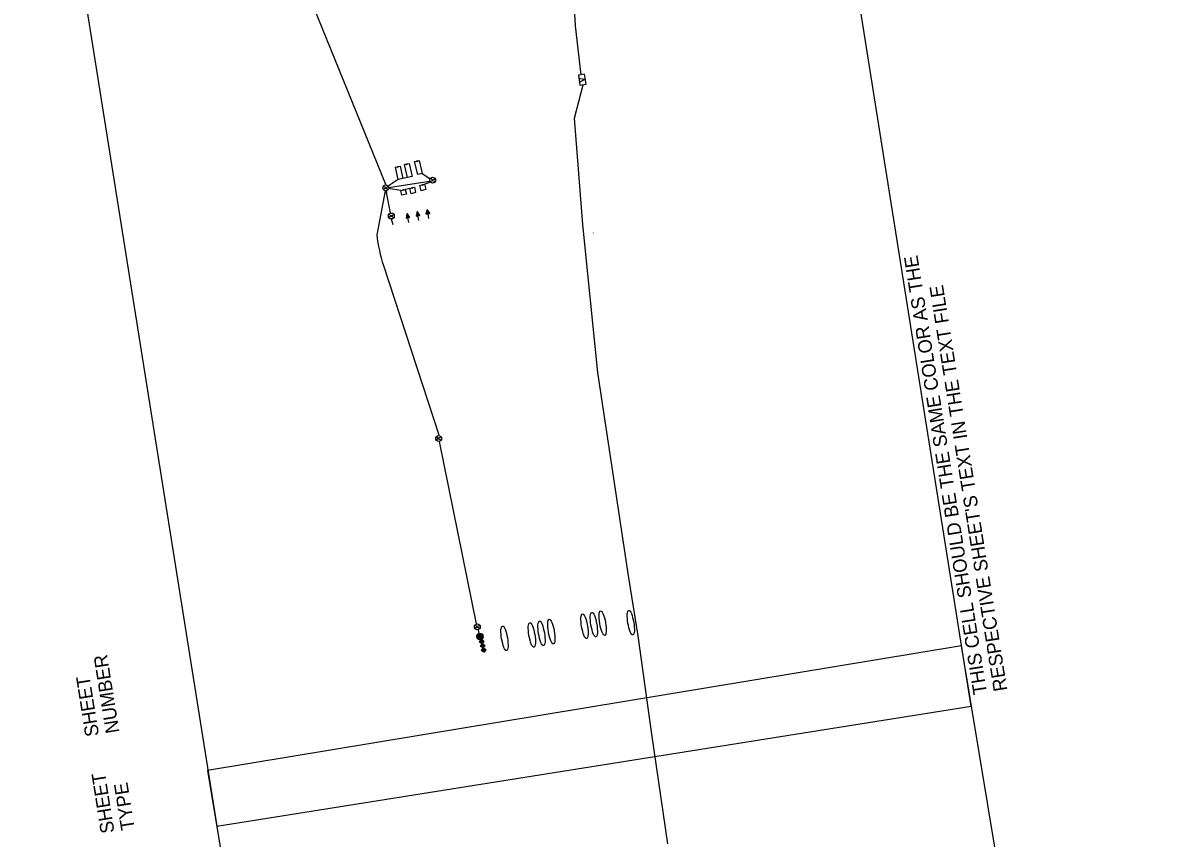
# Model space of a CAD drawing. Extents: x 601462 to 605493, y 331960 to 402715.
# Drawn here: x 603749 to 605204, y 337841 to 338882 of the extents above; entities that cross this region are included whole.
import ezdxf

# ---------------------------------------------------------------- set-up
doc = ezdxf.new("R2010")
doc.units = 0
for name, color, linetype in [('Default', 7, 'Continuous'), ('P_FTMS', 7, 'Continuous'), ('P_FTMSConduit', 7, 'Continuous'), ('P_MISC_TXT_2A (Construction)', 7, 'Continuous'), ('P_MISC_TXT_2B (Construction)', 7, 'Continuous')]:
    doc.layers.add(name, color=color, linetype=linetype)

# ---------------------------------------------------------------- blocks, each defined once
blk = doc.blocks.new('POINT_DISPLAY')
at = {"layer": 'Default'}
blk.add_line((0, 0), (0, 0), dxfattribs=at)
blk = doc.blocks.new('_U222')
at = {"layer": 'P_FTMS'}
for p, q in [((-4.5, 3.2), (1.5, -0.2)), ((-4.4, 2.8), (1.3, -0.4)), ((-4.3, 3.5), (1.8, 0)), ((-3.9, 3.4), (-4.3, 2.6)), ((-4.3, 2.4), (1, -0.6)), ((-3.5, 3.4), (-4.2, 2.2)), ((-4.2, 2), (0.7, -0.8)), ((-3.2, 3.3), (-4.1, 1.7)), ((-4.1, 1.6), (0.5, -1)), ((-2.9, 3.3), (-4, 1.3)), ((-4, 1.2), (0.2, -1.2)), ((-2.6, 3.2), (-3.9, 0.9)), ((-2.2, 3.2), (-3.8, 0.5)), ((-3.8, 0.7), (0, -1.4)), ((-1.9, 3.2), (-3.7, 0.1)), ((-3.7, 0.3), (-0.3, -1.6)), ((-3.5, 3.4), (2, 0.2)), ((-1.6, 3.1), (-3.5, -0.3)), ((-1.3, 3.1), (-3.4, -0.7)), ((-0.9, 3), (-3.3, -1.2)), ((-0.6, 3), (-3.2, -1.6)), ((-0.3, 2.9), (-3.1, -2)), ((0, 2.9), (-3, -2.4)), ((0.4, 2.8), (-2.9, -2.8)), ((-2.7, 3.3), (2.3, 0.4)), ((0.7, 2.8), (-2.7, -3.2)), ((1, 2.8), (-2.5, -3.4)), ((-1.9, 3.2), (2.5, 0.6)), ((1.3, 2.7), (-1.8, -2.9)), ((1.7, 2.7), (-1.2, -2.3)), ((-1.1, 3), (2.8, 0.8)), ((2, 2.6), (-0.5, -1.8)), ((-0.3, 2.9), (3.1, 1)), ((2.3, 2.6), (0.1, -1.3)), ((0.5, 2.8), (3.3, 1.2)), ((2.6, 2.5), (0.7, -0.8)), ((1.3, 2.7), (3.6, 1.4)), ((3, 2.5), (1.4, -0.3)), ((3.3, 2.4), (2, 0.2)), ((2.2, 2.6), (3.8, 1.6)), ((3.6, 2.4), (2.7, 0.7)), ((3, 2.5), (4.1, 1.8)), ((3.9, 2.3), (3.3, 1.2)), ((3.8, 2.4), (4.3, 2.1)), ((4.3, 2.3), (4, 1.7)), ((-3.6, -0.1), (-0.5, -1.8)), ((-3.5, -0.5), (-0.8, -2)), ((-3.4, -0.9), (-1.1, -2.2)), ((-3.3, -1.3), (-1.3, -2.4)), ((-3.2, -1.7), (-1.6, -2.7)), ((-3, -2.2), (-1.8, -2.9)), ((-2.9, -2.6), (-2.1, -3.1)), ((-2.8, -3), (-2.3, -3.3)), ((-2.7, -3.4), (-2.6, -3.5))]:
    blk.add_line(p, q, dxfattribs=at)
blk.add_lwpolyline([(-4.6, 3.5), (4.6, 2.3), (-2.7, -3.5)], close=True, dxfattribs=at)
blk.add_blockref('POINT_DISPLAY', (4.6, 2.3), dxfattribs=at)
blk = doc.blocks.new('FMD')
at = {"layer": 'P_FTMS'}
for p, q in [((16.9, 17.6), (-16.9, 17.6)), ((-16.1, 16.1), (-16.1, 18.4)), ((16.1, 16.1), (-16.1, 16.1)), ((15.5, 19), (-15.5, 19)), ((-14.6, 14.6), (-14.6, 19.9)), ((14.6, 14.6), (-14.6, 14.6)), ((14, 20.5), (-14, 20.5)), ((-13.2, 13.2), (-13.2, 21.3)), ((13.2, 13.2), (-13.2, 13.2)), ((12.5, 21.9), (-12.5, 21.9)), ((-11.7, 11.7), (-11.7, 22.8)), ((11.7, 11.7), (-11.7, 11.7)), ((11.1, 23.4), (-11.1, 23.4)), ((-10.2, 10.2), (-10.2, 24.2)), ((10.2, 10.2), (-10.2, 10.2)), ((9.6, 24.9), (-9.6, 24.9)), ((-8.8, 8.8), (-8.8, 25.7)), ((8.8, 8.8), (-8.8, 8.8)), ((8.2, 26.3), (-8.2, 26.3)), ((-7.3, 7.3), (-7.3, 27.2)), ((7.3, 7.3), (-7.3, 7.3)), ((6.7, 27.8), (-6.7, 27.8)), ((-5.9, 5.9), (-5.9, 28.6)), ((5.9, 5.9), (-5.9, 5.9)), ((5.2, 29.3), (-5.2, 29.3)), ((-4.4, 4.4), (-4.4, 30.1)), ((4.4, 4.4), (-4.4, 4.4)), ((3.8, 30.7), (-3.8, 30.7)), ((-2.9, 2.9), (-2.9, 31.6)), ((2.9, 2.9), (-2.9, 2.9)), ((2.3, 32.2), (-2.3, 32.2)), ((-1.5, 1.5), (-1.5, 33)), ((1.5, 1.5), (-1.5, 1.5)), ((0.8, 33.6), (-0.8, 33.6)), ((0, 0), (0, 34.5)), ((1.5, 1.5), (1.5, 33)), ((2.9, 2.9), (2.9, 31.6)), ((4.4, 4.4), (4.4, 30.1)), ((5.9, 5.9), (5.9, 28.6)), ((7.3, 7.3), (7.3, 27.2)), ((8.8, 8.8), (8.8, 25.7)), ((10.2, 10.2), (10.2, 24.2)), ((11.7, 11.7), (11.7, 22.8)), ((13.2, 13.2), (13.2, 21.3)), ((14.6, 14.6), (14.6, 19.9)), ((16.1, 16.1), (16.1, 18.4))]:
    blk.add_line(p, q, dxfattribs=at)
blk.add_lwpolyline([(-17.2, 17.2), (0, 34.5), (17.2, 17.2), (0, 0)], close=True, dxfattribs=at)
blk = doc.blocks.new('FTMS_FCV')
at = {"layer": 'P_FTMS'}
blk.add_line((12.7, 16.3), (0.6, -21.9), dxfattribs=at)
blk.add_lwpolyline([(39.1, 24.4), (-39.1, 24.4), (-39.1, -24.4), (39.1, -24.4)], close=True, dxfattribs=at)
blk.add_lwpolyline([(-12.1, 16.2), (0.6, -21.9)], dxfattribs=at)

msp = doc.modelspace()

# ---------------------------------------------------------------- linework, layer by layer
at = {"layer": 'P_FTMS'}
for p, q in [((604258.4, 338689.6), (604268.3, 338683.1)), ((604227.9, 338682), (604214.9, 338673.4)), ((604239.6, 338684.5), (604233.8, 338683.4)), ((604261.4, 338675.8), (604268.3, 338678.6)), ((604231, 338667.8), (604215.5, 338670.4)), ((604242.6, 338670.6), (604236.8, 338669.2)), ((604241.3, 338627.1), (604240.1, 338633.1)), ((604254.1, 338629.6), (604252.9, 338635.6)), ((604266.9, 338632), (604265.8, 338638.1)), ((604328.1, 338099.6), (604334.4, 338102)), ((604328.1, 338099.4), (604334.6, 338101.9)), ((604328.1, 338099.1), (604334.8, 338101.7)), ((604328.1, 338098.8), (604335, 338101.5)), ((604328.1, 338098.6), (604335.2, 338101.3)), ((604328.1, 338098.3), (604335.3, 338101.1)), ((604328.1, 338098.1), (604335.4, 338100.9)), ((604329.7, 338095.6), (604328.1, 338099.6)), ((604329.3, 338095.9), (604328.1, 338099.1)), ((604328.9, 338096.4), (604328.1, 338098.5)), ((604328.2, 338099.9), (604334.2, 338102.2)), ((604328.2, 338097.8), (604335.6, 338100.7)), ((604330, 338095.4), (604328.2, 338100)), ((604328.3, 338100.2), (604333.9, 338102.4)), ((604328.3, 338097.6), (604335.7, 338100.5)), ((604328.3, 338097.4), (604335.8, 338100.3)), ((604328.4, 338100.5), (604333.6, 338102.5)), ((604330.4, 338095.2), (604328.4, 338100.4)), ((604328.4, 338097.2), (604335.9, 338100)), ((604330.7, 338095.1), (604328.5, 338100.7)), ((604328.5, 338097), (604335.9, 338099.8)), ((604328.6, 338100.8), (604333.2, 338102.6)), ((604328.6, 338096.7), (604336, 338099.6)), ((604331, 338095), (604328.7, 338100.9)), ((604328.8, 338101.2), (604332.8, 338102.7)), ((604331.2, 338094.9), (604328.8, 338101.2)), ((604328.8, 338096.5), (604336, 338099.3)), ((604328.9, 338096.3), (604336, 338099.1)), ((604331.5, 338094.9), (604329, 338101.4)), ((604329.1, 338096.1), (604336, 338098.8)), ((604329.2, 338101.6), (604332.4, 338102.8)), ((604331.8, 338094.8), (604329.2, 338101.6)), ((604329.3, 338096), (604336, 338098.6)), ((604332, 338094.8), (604329.4, 338101.8)), ((604329.5, 338095.8), (604336, 338098.3)), ((604332.3, 338094.8), (604329.6, 338101.9)), ((604329.7, 338102), (604331.7, 338102.8)), ((604329.7, 338095.6), (604336, 338098)), ((604332.5, 338094.9), (604329.8, 338102.1)), ((604329.9, 338095.4), (604335.9, 338097.7)), ((604332.8, 338094.9), (604330, 338102.2)), ((604333, 338095), (604330.2, 338102.3)), ((604330.2, 338095.3), (604335.8, 338097.4)), ((604333.3, 338095), (604330.4, 338102.5)), ((604330.5, 338095.1), (604335.7, 338097.1)), ((604333.5, 338095.1), (604330.6, 338102.5)), ((604333.7, 338095.2), (604330.8, 338102.6)), ((604330.8, 338095), (604335.5, 338096.8)), ((604333.9, 338095.3), (604331.1, 338102.7)), ((604334.1, 338095.4), (604331.3, 338102.7)), ((604331.3, 338094.9), (604335.3, 338096.5)), ((604334.3, 338095.6), (604331.6, 338102.8)), ((604331.7, 338094.9), (604334.9, 338096.1)), ((604334.5, 338095.7), (604331.8, 338102.8)), ((604334.7, 338095.9), (604332.1, 338102.8)), ((604334.9, 338096.1), (604332.3, 338102.8)), ((604332.4, 338094.9), (604334.4, 338095.6)), ((604335.1, 338096.2), (604332.6, 338102.8)), ((604335.3, 338096.5), (604332.9, 338102.7)), ((604335.4, 338096.7), (604333.1, 338102.7)), ((604335.6, 338097), (604333.4, 338102.6)), ((604335.7, 338097.3), (604333.7, 338102.4)), ((604335.9, 338097.6), (604334.1, 338102.3)), ((604336, 338098), (604334.4, 338102)), ((604336, 338098.5), (604334.8, 338101.7)), ((604336, 338099.2), (604335.2, 338101.2))]:
    msp.add_line(p, q, dxfattribs=at)
for points in [[(604248.7, 338704.8), (604254.6, 338706.2), (604258.4, 338689.6), (604252.6, 338688.2), (604252.6, 338688.2), (604248.7, 338704.8)], [(604224.3, 338697.6), (604230.1, 338699), (604233.8, 338683.4), (604227.9, 338682), (604224.3, 338697.6)], [(604235.8, 338701), (604241.6, 338702.4), (604245.5, 338685.8), (604239.6, 338684.5), (604239.6, 338684.5), (604235.8, 338701)], [(604257.1, 338667.6), (604255.5, 338674.4), (604255.5, 338674.4), (604261.4, 338675.8), (604263, 338669), (604257.1, 338667.6)], [(604231, 338667.8), (604236.8, 338669.2), (604238.2, 338663.4), (604232.4, 338662), (604231, 338667.8)], [(604244.2, 338663.8), (604242.6, 338670.6), (604242.6, 338670.6), (604248.4, 338672), (604250, 338665.2), (604244.2, 338663.8)]]:
    msp.add_lwpolyline(points, dxfattribs=at)
for centre, radius in [((604211.9, 338671.2), 3.75), ((604271.7, 338681.1), 3.75), ((604219, 338635.4), 3.75), ((604279.4, 338351.5), 3.75), ((604328.7, 338111.2), 3.75), ((604332, 338098.8), 4)]:
    msp.add_circle(centre, radius, dxfattribs=at)
for centre, start, end in [((604271.6, 338676.6), 34.9457, 141.2014), ((604271.9, 338685.6), 214.9457, 321.2014), ((604211.8, 338666.7), 34.9457, 141.2014), ((604212.1, 338675.7), 214.9457, 321.2014), ((604218.8, 338630.9), 34.1999, 140.4555), ((604219.2, 338639.9), 214.1999, 320.4555), ((604279.4, 338356), 216.2095, 322.4651), ((604279.3, 338347), 36.2095, 142.4651), ((604328.8, 338115.7), 216.2095, 322.4651), ((604328.7, 338106.7), 36.2095, 142.4651)]:
    msp.add_arc(centre, 3.75, start, end, dxfattribs=at)
for centre in [(604465.5, 338111.9), (604477.4, 338113.9), (604488.6, 338115.8), (604524.6, 338116.4), (604363.4, 338096.4), (604398.3, 338100.7), (604410.6, 338102.8), (604423.2, 338105)]:
    msp.add_ellipse(centre, major_axis=(-2.7, 15.7), ratio=0.23471, dxfattribs=at)
at = {"layer": 'P_FTMSConduit'}
for p, q in [((604453.8, 338878.7), (604442.7, 339066.3)), ((604212.1, 338675.7), (604091.9, 338971.5)), ((604461.4, 338815.5), (604453.9, 338878.1)), ((604452.7, 338760), (604463.7, 338802.9)), ((604463.3, 338624.5), (604452.7, 338760)), ((604250.6, 338705.8), (604252.7, 338705.1)), ((604250.9, 338704.7), (604252.5, 338706.3)), ((604226.2, 338698.6), (604228.3, 338697.9)), ((604226.4, 338697.5), (604228, 338699.1)), ((604237.6, 338702.1), (604239.8, 338701.4)), ((604237.9, 338701), (604239.5, 338702.5)), ((604215.5, 338671.9), (604267.7, 338680)), ((604257.4, 338675.4), (604259.5, 338674.7)), ((604257.7, 338674.3), (604259.3, 338675.9)), ((604211.2, 338667.5), (604200.4, 338611.2)), ((604233.1, 338668.9), (604235.2, 338668.2)), ((604233.4, 338667.8), (604235, 338669.4)), ((604244.5, 338671.7), (604246.6, 338671)), ((604244.7, 338670.6), (604246.3, 338672.2)), ((604221.2, 338624.1), (604219.4, 338631.4)), ((604482.7, 338435.8), (604463.3, 338624.5)), ((604208.9, 338572.2), (604279.4, 338356)), ((604522.2, 338173.8), (604482.7, 338435.8)), ((604327.8, 338115.1), (604280.3, 338347.6)), ((604534.1, 338099.6), (604522.2, 338173.8)), ((604329.6, 338107.3), (604330.6, 338102.6)), ((604551.5, 337974.3), (604534.1, 338099.6)), ((604571.9, 337834.4), (604551.5, 337974.3))]:
    msp.add_line(p, q, dxfattribs=at)
for points in [[(604212.5, 338667.4), (604212.6, 338666.7)], [(604217.9, 338639.3), (604212.9, 338665.3)]]:
    msp.add_lwpolyline(points, dxfattribs=at)
for centre, radius, start, end in [((604429, 338875.8), 25, 5.4088, 6.7354), ((604286.5, 338679.7), 75, 189.4195, 191.0696), ((604399.1, 338634.2), 200, 186.6238, 198.0562), ((604501.5, 338616), 25, 184.6524, 185.4069)]:
    msp.add_arc(centre, radius, start, end, dxfattribs=at)
at = {"layer": 'P_MISC_TXT_2A (Construction)'}
msp.add_lwpolyline([(604959, 338009.7), (604711.6, 339565.2), (603748.7, 339412.1), (603996.1, 337856.6)], close=True, dxfattribs=at)
at = {"layer": 'P_MISC_TXT_2B (Construction)'}
msp.add_lwpolyline([(605203.9, 336533.1), (604946.5, 338086.9), (603984.6, 337927.6), (604242.1, 336373.7)], close=True, dxfattribs=at)

# ---------------------------------------------------------------- block references
at = {"layer": 'P_FTMS'}
for name, p, xscale, yscale, rotation in [('FTMS_FCV', (604462.6, 338809.2), 0.16404166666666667, 0.1640416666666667, 99.05313895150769), ('_U222', (604239.1, 338635.2), 0.6330710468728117, -0.6330710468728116, 116.25578027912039), ('_U222', (604251.9, 338637.7), 0.6330710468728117, -0.6330710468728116, 116.25578027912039), ('_U222', (604265.9, 338640.4), 0.6330710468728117, 0.6330710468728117, 85.60583638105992), ('FMD', (604336.9, 338093), 0.16404166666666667, 0.1640416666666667, 103.08542551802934), ('FMD', (604338.2, 338087.5), 0.16404166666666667, 0.1640416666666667, 103.08542551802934), ('FMD', (604339.5, 338082), 0.16404166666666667, 0.1640416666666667, 103.08542551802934)]:
    msp.add_blockref(name, p, dxfattribs=dict(at, xscale=xscale, yscale=yscale, rotation=rotation))

# ---------------------------------------------------------------- texts
at = {"layer": 'P_MISC_TXT_2A (Construction)'}
for s, p in [('THIS CELL SHOULD BE THE SAME COLOR AS THE', (604979.3, 338026.1)), ("RESPECTIVE SHEET'S TEXT IN THE TEXT FILE", (605005.2, 338030.2)), ('NUMBER', (603872.1, 337976.6)), ('SHEET', (603846.1, 337972.5)), ('SHEET', (603865.8, 337849)), ('TYPE', (603891.7, 337853.1))]:
    msp.add_text(s, height=17.5, rotation=99.0354, dxfattribs=at).set_placement(p)

doc.saveas('drawing.dxf')
